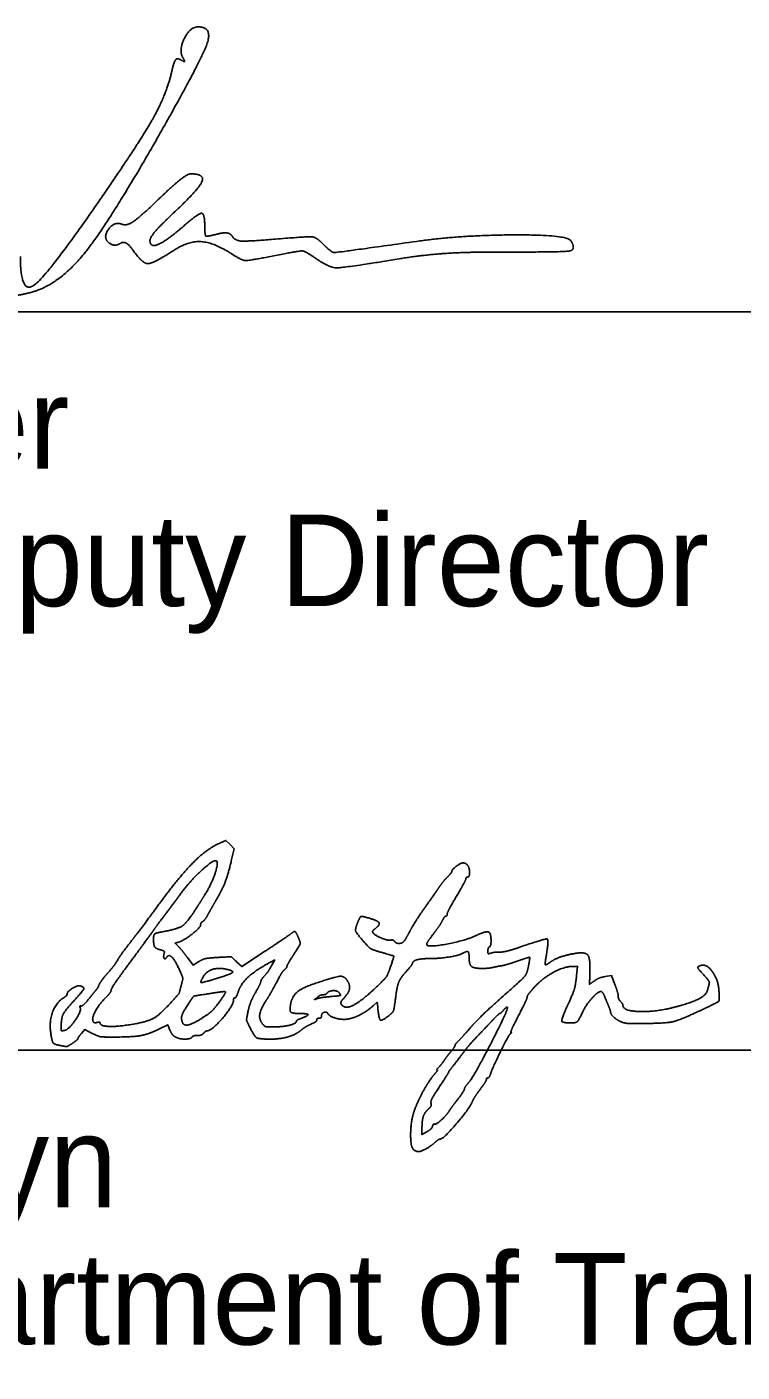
# Model space of a CAD drawing. Extents: x 0 to 34, y 0 to 22.
# Drawn here: x 25.807 to 26.9, y 8.607 to 10.664 of the extents above; entities that cross this region are included whole.
import ezdxf

# ---------------------------------------------------------------- set-up
doc = ezdxf.new("R2010")
doc.units = 0
for name, color, linetype in [('Default', 7, 'Continuous'), ('SH_Data', 7, 'Continuous'), ('SH_Text', 7, 'Continuous')]:
    doc.layers.add(name, color=color, linetype=linetype)

msp = doc.modelspace()

# ---------------------------------------------------------------- linework, layer by layer
at = {"layer": 'Default'}
for points in [[(26.0982, 9.4141), (26.1108, 9.42), (26.1172, 9.4136), (26.1235, 9.4072), (26.1191, 9.3885)], [(26.0383, 9.2641), (26.0332, 9.2626), (26.0384, 9.2574)], [(26.0521, 9.2407), (26.0606, 9.2292), (26.0694, 9.2345)], [(26.1272, 9.2344), (26.1354, 9.2268), (26.1716, 9.2509)], [(26.1811, 9.2292), (26.1856, 9.2371), (26.18, 9.2342)], [(26.647, 9.2133), (26.6484, 9.2271), (26.6406, 9.2271)], [(26.6908, 9.2116), (26.7005, 9.2132), (26.7055, 9.1996)], [(26.3429, 9.1655), (26.3422, 9.1723), (26.3363, 9.1672)], [(26.0252, 9.1299), (26.0219, 9.1379), (26.0081, 9.1311)], [(25.9066, 9.1248), (25.8951, 9.1306), (25.8901, 9.1248)], [(26.4106, 8.9794), (26.4106, 8.97), (26.4181, 8.9743)]]:
    msp.add_lwpolyline(points, dxfattribs=at)
for points in [[(26.0086, 9.3222), (26.0383, 9.3628), (26.0801, 9.4057), (26.0982, 9.4141)], [(26.0967, 9.3883), (26.0931, 9.392), (26.0545, 9.3562), (26.0391, 9.3349)], [(26.0784, 9.3363), (26.0879, 9.3511), (26.0998, 9.3852), (26.0967, 9.3883)], [(26.1191, 9.3885), (26.1141, 9.3674), (26.105, 9.3438), (26.0955, 9.3279)], [(26.4562, 9.3722), (26.4562, 9.375), (26.4694, 9.3853), (26.4731, 9.3854)], [(26.4731, 9.3854), (26.4752, 9.3854), (26.4781, 9.3842), (26.4797, 9.3826)], [(26.4797, 9.3826), (26.4832, 9.3791), (26.4836, 9.3639), (26.4802, 9.3639)], [(26.4358, 9.3469), (26.4398, 9.3527), (26.446, 9.3605), (26.4496, 9.3641)], [(26.4496, 9.3641), (26.4532, 9.3677), (26.4562, 9.3714), (26.4562, 9.3722)], [(26.4778, 9.3613), (26.4778, 9.36), (26.4713, 9.3479), (26.4634, 9.3345)], [(26.4802, 9.3639), (26.4789, 9.3639), (26.4778, 9.3627), (26.4778, 9.3613)], [(26.4142, 9.3159), (26.4221, 9.3271), (26.4319, 9.341), (26.4358, 9.3469)], [(25.9685, 9.2688), (25.9773, 9.2801), (25.9954, 9.3042), (26.0086, 9.3222)], [(26.0391, 9.3349), (26.0356, 9.33), (26.0261, 9.3173), (26.0182, 9.3068)], [(26.0679, 9.3196), (26.0712, 9.3248), (26.0759, 9.3323), (26.0784, 9.3363)], [(26.0955, 9.3279), (26.092, 9.3219), (26.0868, 9.3127), (26.084, 9.3075)], [(26.4634, 9.3345), (26.4555, 9.3211), (26.449, 9.3087), (26.449, 9.307)], [(26.0182, 9.3068), (26.0103, 9.2964), (26.0022, 9.2853), (26.0002, 9.2824)], [(26.0181, 9.2809), (26.0387, 9.2847), (26.0527, 9.2956), (26.0679, 9.3196)], [(26.084, 9.3075), (26.0811, 9.3022), (26.0773, 9.297), (26.0755, 9.2959)], [(26.3122, 9.2941), (26.3159, 9.3032), (26.319, 9.3042), (26.3317, 9.3004)], [(26.3317, 9.3004), (26.3437, 9.2969), (26.3466, 9.2907), (26.3389, 9.2849)], [(26.3928, 9.2823), (26.3966, 9.2895), (26.4063, 9.3046), (26.4142, 9.3159)], [(26.447, 9.3039), (26.4459, 9.3039), (26.4436, 9.3009), (26.4418, 9.2973)], [(26.449, 9.307), (26.449, 9.3053), (26.4481, 9.3039), (26.447, 9.3039)], [(26.0002, 9.2824), (25.9982, 9.2794), (25.9829, 9.2585), (25.9661, 9.2358)], [(26.0002, 9.2688), (26.0002, 9.2757), (26.0043, 9.2785), (26.0181, 9.2809)], [(26.0722, 9.2905), (26.0722, 9.2868), (26.0464, 9.2667), (26.0383, 9.2641)], [(26.0755, 9.2959), (26.0737, 9.2949), (26.0722, 9.2925), (26.0722, 9.2905)], [(26.2107, 9.2775), (26.2153, 9.2812), (26.2176, 9.2803), (26.2206, 9.2737)], [(26.322, 9.2647), (26.3104, 9.2778), (26.3082, 9.2845), (26.3122, 9.2941)], [(26.3389, 9.2849), (26.3362, 9.2828), (26.3347, 9.28), (26.3357, 9.2786)], [(26.3836, 9.2661), (26.3848, 9.2677), (26.389, 9.275), (26.3928, 9.2823)], [(26.4418, 9.2973), (26.44, 9.2936), (26.4338, 9.2845), (26.4282, 9.2771)], [(26.4954, 9.2752), (26.5084, 9.2814), (26.5162, 9.2783), (26.5162, 9.2669)], [(25.9469, 9.2394), (25.9499, 9.2442), (25.9596, 9.2574), (25.9685, 9.2688)], [(26.0112, 9.2524), (26.004, 9.2542), (26.0002, 9.2599), (26.0002, 9.2688)], [(26.1716, 9.2509), (26.1915, 9.2642), (26.2091, 9.2761), (26.2107, 9.2775)], [(26.2206, 9.2737), (26.225, 9.2641), (26.2241, 9.26), (26.2138, 9.2442)], [(26.3454, 9.2496), (26.3347, 9.2527), (26.3297, 9.2558), (26.322, 9.2647)], [(26.3357, 9.2786), (26.3383, 9.2748), (26.3583, 9.2666), (26.3629, 9.2674)], [(26.3629, 9.2674), (26.3651, 9.2678), (26.3677, 9.267), (26.3685, 9.2656)], [(26.3685, 9.2656), (26.3707, 9.2621), (26.3807, 9.2624), (26.3836, 9.2661)], [(26.4282, 9.2771), (26.4225, 9.2696), (26.4178, 9.2623), (26.4178, 9.261)], [(26.4178, 9.261), (26.4178, 9.2557), (26.4774, 9.2667), (26.4954, 9.2752)], [(26.5162, 9.2669), (26.5162, 9.2623), (26.5151, 9.2579), (26.5138, 9.2571)], [(26.5586, 9.2561), (26.5989, 9.27), (26.6048, 9.2684), (26.6007, 9.2445)], [(25.9306, 9.2175), (25.9372, 9.2249), (25.9415, 9.2306), (25.9469, 9.2394)], [(26.0163, 9.2462), (26.0172, 9.2497), (26.016, 9.2512), (26.0112, 9.2524)], [(26.0206, 9.2414), (26.0182, 9.2375), (26.015, 9.2411), (26.0163, 9.2462)], [(26.0394, 9.2228), (26.0332, 9.2365), (26.0235, 9.2461), (26.0206, 9.2414)], [(26.0384, 9.2574), (26.0412, 9.2546), (26.0474, 9.2471), (26.0521, 9.2407)], [(26.0694, 9.2345), (26.0759, 9.2383), (26.0835, 9.24), (26.0986, 9.2409)], [(26.0986, 9.2409), (26.1189, 9.2421), (26.1191, 9.242), (26.1272, 9.2344)], [(26.2138, 9.2442), (26.2085, 9.236), (26.2042, 9.2284), (26.2042, 9.2273)], [(26.3622, 9.2258), (26.3679, 9.2426), (26.3675, 9.2432), (26.3454, 9.2496)], [(26.4205, 9.2391), (26.409, 9.2391), (26.3962, 9.2353), (26.3962, 9.2319)], [(26.4712, 9.2464), (26.4656, 9.2435), (26.4354, 9.2391), (26.4205, 9.2391)], [(26.4826, 9.2417), (26.4826, 9.2491), (26.4789, 9.2506), (26.4712, 9.2464)], [(26.5019, 9.2241), (26.4895, 9.2241), (26.4826, 9.2304), (26.4826, 9.2417)], [(26.5138, 9.2571), (26.5125, 9.2562), (26.5114, 9.2534), (26.5114, 9.2508)], [(26.5114, 9.2508), (26.5114, 9.2468), (26.5124, 9.2463), (26.5168, 9.2477)], [(26.5168, 9.2477), (26.5198, 9.2486), (26.5256, 9.2493), (26.5298, 9.2491)], [(26.5298, 9.2491), (26.5339, 9.249), (26.5469, 9.2521), (26.5586, 9.2561)], [(26.5738, 9.2295), (26.5759, 9.241), (26.5742, 9.2414), (26.5532, 9.2342)], [(26.6007, 9.2445), (26.5994, 9.2369), (26.5987, 9.2303), (26.5991, 9.2298)], [(26.6067, 9.2337), (26.6139, 9.2387), (26.6322, 9.245), (26.6458, 9.2472)], [(26.6458, 9.2472), (26.6605, 9.2495), (26.6681, 9.2391), (26.6673, 9.2178)], [(25.9162, 9.1971), (25.9162, 9.1987), (25.9254, 9.2117), (25.9306, 9.2175)], [(25.9661, 9.2358), (25.9493, 9.2132), (25.9355, 9.193), (25.9354, 9.1911)], [(26.0427, 9.1983), (26.0452, 9.2081), (26.0449, 9.2103), (26.0394, 9.2228)], [(26.1104, 9.2231), (26.0996, 9.2253), (26.0822, 9.2202), (26.0778, 9.2136)], [(26.0998, 9.2096), (26.119, 9.2155), (26.123, 9.2206), (26.1104, 9.2231)], [(26.18, 9.2342), (26.1566, 9.2216), (26.1339, 9.201), (26.1298, 9.1885)], [(26.1683, 9.211), (26.1738, 9.217), (26.1763, 9.2206), (26.1811, 9.2292)], [(26.2007, 9.2223), (26.1987, 9.2207), (26.1956, 9.2165), (26.1938, 9.213)], [(26.2042, 9.2273), (26.2042, 9.2262), (26.2026, 9.2239), (26.2007, 9.2223)], [(26.3439, 9.1985), (26.3543, 9.2085), (26.3585, 9.2147), (26.3622, 9.2258)], [(26.3869, 9.2198), (26.3784, 9.2104), (26.3727, 9.1978), (26.3711, 9.1851)], [(26.3962, 9.2319), (26.3962, 9.231), (26.392, 9.2256), (26.3869, 9.2198)], [(26.5186, 9.2255), (26.5153, 9.2247), (26.5078, 9.2241), (26.5019, 9.2241)], [(26.5318, 9.2281), (26.5279, 9.2275), (26.5219, 9.2263), (26.5186, 9.2255)], [(26.529, 9.1766), (26.5645, 9.2081), (26.5714, 9.2163), (26.5738, 9.2295)], [(26.5532, 9.2342), (26.5454, 9.2315), (26.5358, 9.2287), (26.5318, 9.2281)], [(26.6406, 9.2271), (26.6279, 9.2271), (26.5942, 9.2086), (26.582, 9.1951)], [(26.5991, 9.2298), (26.5996, 9.2293), (26.603, 9.2311), (26.6067, 9.2337)], [(26.6673, 9.2178), (26.6667, 9.1994), (26.6665, 9.1997), (26.6743, 9.2052)], [(26.8374, 9.2185), (26.8321, 9.2241), (26.8319, 9.2268), (26.8365, 9.2285)], [(26.8365, 9.2285), (26.8451, 9.2318), (26.8635, 9.2069), (26.8645, 9.1906)], [(26.8465, 9.1893), (26.8505, 9.2011), (26.849, 9.206), (26.8374, 9.2185)], [(25.8682, 9.185), (25.8683, 9.1888), (25.885, 9.1988), (25.8888, 9.1973)], [(25.8888, 9.1973), (25.8948, 9.195), (25.8925, 9.1901), (25.8782, 9.1742)], [(25.9138, 9.1928), (25.9151, 9.1944), (25.9162, 9.1963), (25.9162, 9.1971)], [(26.023, 9.1678), (26.0391, 9.1853), (26.0394, 9.1859), (26.0427, 9.1983)], [(26.0778, 9.2136), (26.0708, 9.2029), (26.0754, 9.2021), (26.0998, 9.2096)], [(26.1559, 9.1869), (26.1603, 9.1946), (26.1641, 9.2023), (26.1643, 9.204)], [(26.1643, 9.204), (26.1646, 9.2058), (26.1664, 9.2089), (26.1683, 9.211)], [(26.1938, 9.213), (26.1856, 9.1976), (26.1779, 9.1838), (26.1717, 9.1741)], [(26.21, 9.1703), (26.2121, 9.1815), (26.2283, 9.1949), (26.2476, 9.2013)], [(26.2476, 9.2013), (26.2794, 9.2119), (26.2929, 9.2123), (26.2979, 9.2029)], [(26.2869, 9.1696), (26.2923, 9.161), (26.319, 9.1745), (26.3439, 9.1985)], [(26.2979, 9.2029), (26.3012, 9.1968), (26.2977, 9.1854), (26.2903, 9.1775)], [(26.6323, 9.1654), (26.6413, 9.1853), (26.6454, 9.1985), (26.647, 9.2133)], [(26.6743, 9.2052), (26.678, 9.2079), (26.6855, 9.2108), (26.6908, 9.2116)], [(26.7055, 9.1996), (26.7083, 9.1922), (26.7106, 9.184), (26.7106, 9.1815)], [(25.8434, 9.1234), (25.8404, 9.142), (25.8512, 9.172), (25.8636, 9.1797)], [(25.8636, 9.1797), (25.8661, 9.1813), (25.8682, 9.1837), (25.8682, 9.185)], [(25.8894, 9.1666), (25.8908, 9.1662), (25.8963, 9.1713), (25.9017, 9.1779)], [(25.9017, 9.1779), (25.907, 9.1845), (25.9125, 9.1912), (25.9138, 9.1928)], [(25.928, 9.1803), (25.9182, 9.1707), (25.9058, 9.1486), (25.9076, 9.1439)], [(25.9354, 9.1911), (25.9353, 9.1891), (25.932, 9.1843), (25.928, 9.1803)], [(26.0806, 9.1848), (26.0628, 9.1822), (26.0608, 9.1811), (26.0535, 9.1699)], [(26.098, 9.1875), (26.0924, 9.1866), (26.0846, 9.1854), (26.0806, 9.1848)], [(26.103, 9.1758), (26.1108, 9.1872), (26.1099, 9.1893), (26.098, 9.1875)], [(26.1246, 9.1791), (26.1235, 9.1791), (26.1226, 9.1777), (26.1226, 9.1761)], [(26.1298, 9.1885), (26.128, 9.1833), (26.1257, 9.1791), (26.1246, 9.1791)], [(26.1449, 9.1591), (26.1465, 9.1668), (26.1514, 9.1793), (26.1559, 9.1869)], [(26.2509, 9.1801), (26.2463, 9.1763), (26.2463, 9.1763), (26.251, 9.178)], [(26.2597, 9.1839), (26.2574, 9.1839), (26.2534, 9.1822), (26.2509, 9.1801)], [(26.251, 9.178), (26.2537, 9.1789), (26.2612, 9.1801), (26.2678, 9.1807)], [(26.2652, 9.186), (26.2645, 9.1848), (26.262, 9.1839), (26.2597, 9.1839)], [(26.2837, 9.1871), (26.2809, 9.1905), (26.2675, 9.1897), (26.2652, 9.186)], [(26.2678, 9.1807), (26.2845, 9.1823), (26.2869, 9.1832), (26.2837, 9.1871)], [(26.2903, 9.1775), (26.2876, 9.1746), (26.286, 9.1711), (26.2869, 9.1696)], [(26.3711, 9.1851), (26.3682, 9.1626), (26.3665, 9.1571), (26.3608, 9.1526)], [(26.4849, 9.1338), (26.4921, 9.1422), (26.512, 9.1614), (26.529, 9.1766)], [(26.5714, 9.1805), (26.5714, 9.1789), (26.5655, 9.1661), (26.5582, 9.1519)], [(26.582, 9.1951), (26.5762, 9.1886), (26.5714, 9.1821), (26.5714, 9.1805)], [(26.6838, 9.1887), (26.6795, 9.1887), (26.6613, 9.1682), (26.6565, 9.158)], [(26.6894, 9.1821), (26.6879, 9.1857), (26.6854, 9.1887), (26.6838, 9.1887)], [(26.6953, 9.1679), (26.6936, 9.1721), (26.6909, 9.1784), (26.6894, 9.1821)], [(26.7106, 9.1815), (26.7106, 9.179), (26.7122, 9.1754), (26.7142, 9.1734)], [(26.7977, 9.1651), (26.8213, 9.1713), (26.8443, 9.1827), (26.8465, 9.1893)], [(26.8645, 9.1906), (26.8655, 9.1753), (26.8628, 9.1722), (26.8394, 9.1612)], [(25.8782, 9.1742), (25.8645, 9.1591), (25.8595, 9.1489), (25.8589, 9.1351)], [(25.8638, 9.1291), (25.8701, 9.13), (25.8902, 9.1585), (25.8882, 9.1637)], [(25.8882, 9.1637), (25.8874, 9.1656), (25.888, 9.1669), (25.8894, 9.1666)], [(25.9665, 9.1384), (25.9892, 9.1421), (26.0089, 9.1523), (26.023, 9.1678)], [(26.0535, 9.1699), (26.0453, 9.1572), (26.0421, 9.1474), (26.0444, 9.1416)], [(26.0731, 9.1472), (26.0843, 9.1541), (26.0953, 9.1647), (26.103, 9.1758)], [(26.1226, 9.1761), (26.1224, 9.1675), (26.0893, 9.1287), (26.0822, 9.1287)], [(26.1469, 9.1351), (26.1425, 9.1442), (26.1423, 9.1464), (26.1449, 9.1591)], [(26.1717, 9.1741), (26.1638, 9.1615), (26.1615, 9.1463), (26.1666, 9.1395)], [(26.2236, 9.1551), (26.212, 9.1551), (26.208, 9.1596), (26.21, 9.1703)], [(26.2665, 9.1552), (26.2645, 9.1585), (26.257, 9.1554), (26.257, 9.1512)], [(26.3363, 9.1672), (26.327, 9.159), (26.3069, 9.1484), (26.2978, 9.1467)], [(26.3608, 9.1526), (26.3491, 9.1434), (26.3447, 9.1465), (26.3429, 9.1655)], [(26.4823, 9.05), (26.49, 9.0587), (26.5432, 9.1625), (26.5411, 9.1646)], [(26.5354, 9.1605), (26.533, 9.1575), (26.5304, 9.1551), (26.5296, 9.1551)], [(26.5411, 9.1646), (26.5404, 9.1653), (26.5378, 9.1634), (26.5354, 9.1605)], [(26.6396, 9.1407), (26.6251, 9.1407), (26.6235, 9.1461), (26.6323, 9.1654)], [(26.6565, 9.158), (26.6508, 9.1456), (26.646, 9.1407), (26.6396, 9.1407)], [(26.6987, 9.1583), (26.6986, 9.1594), (26.6971, 9.1637), (26.6953, 9.1679)], [(26.7144, 9.1427), (26.7073, 9.1461), (26.6988, 9.1545), (26.6987, 9.1583)], [(26.7142, 9.1734), (26.7162, 9.1714), (26.7178, 9.1687), (26.7178, 9.1674)], [(26.7178, 9.1674), (26.7178, 9.1589), (26.7684, 9.1574), (26.7977, 9.1651)], [(26.8394, 9.1612), (26.8046, 9.1449), (26.7836, 9.1401), (26.7442, 9.1397)], [(25.8589, 9.1351), (25.8587, 9.1295), (25.8595, 9.1285), (25.8638, 9.1291)], [(25.9076, 9.1439), (25.9085, 9.1415), (25.9108, 9.1406), (25.9138, 9.1414)], [(25.9138, 9.1414), (25.9165, 9.1421), (25.9186, 9.1417), (25.9186, 9.1406)], [(25.9186, 9.1406), (25.9186, 9.136), (25.9443, 9.1348), (25.9665, 9.1384)], [(26.0444, 9.1416), (26.0464, 9.1363), (26.06, 9.139), (26.0731, 9.1472)], [(26.1787, 9.1159), (26.1612, 9.116), (26.1542, 9.1203), (26.1469, 9.1351)], [(26.1666, 9.1395), (26.1695, 9.1357), (26.173, 9.1347), (26.1842, 9.1347)], [(26.1842, 9.1347), (26.1982, 9.1347), (26.2186, 9.1398), (26.2186, 9.1433)], [(26.2186, 9.1433), (26.2186, 9.1443), (26.2223, 9.1465), (26.2269, 9.1481)], [(26.2269, 9.1481), (26.2372, 9.1519), (26.2356, 9.1551), (26.2236, 9.1551)], [(26.2444, 9.1405), (26.2371, 9.1372), (26.2294, 9.1327), (26.2252, 9.1292)], [(26.2498, 9.1454), (26.2498, 9.144), (26.2474, 9.1418), (26.2444, 9.1405)], [(26.2534, 9.1479), (26.2514, 9.1479), (26.2498, 9.1468), (26.2498, 9.1454)], [(26.257, 9.1512), (26.257, 9.1494), (26.2554, 9.1479), (26.2534, 9.1479)], [(26.2978, 9.1467), (26.2892, 9.1452), (26.2694, 9.1505), (26.2665, 9.1552)], [(26.5208, 9.1473), (26.5168, 9.143), (26.5062, 9.1319), (26.4974, 9.1226)], [(26.5296, 9.1551), (26.5289, 9.1551), (26.5249, 9.1516), (26.5208, 9.1473)], [(26.5582, 9.1519), (26.5509, 9.1378), (26.5458, 9.1262), (26.5468, 9.1262)], [(26.7442, 9.1397), (26.7293, 9.1395), (26.719, 9.1406), (26.7144, 9.1427)], [(25.8599, 9.1057), (25.849, 9.1077), (25.8452, 9.1118), (25.8434, 9.1234)], [(25.885, 9.1172), (25.885, 9.1163), (25.8812, 9.1129), (25.8766, 9.1098)], [(25.8901, 9.1248), (25.8873, 9.1216), (25.885, 9.1182), (25.885, 9.1172)], [(25.9374, 9.1191), (25.9218, 9.1191), (25.9159, 9.1202), (25.9066, 9.1248)], [(26.0081, 9.1311), (25.9925, 9.1233), (25.9673, 9.1191), (25.9374, 9.1191)], [(26.0335, 9.1193), (26.0308, 9.1207), (26.0271, 9.1255), (26.0252, 9.1299)], [(26.059, 9.1191), (26.057, 9.1159), (26.0395, 9.116), (26.0335, 9.1193)], [(26.0673, 9.1215), (26.0635, 9.1215), (26.0598, 9.1204), (26.059, 9.1191)], [(26.077, 9.1251), (26.0754, 9.1231), (26.071, 9.1215), (26.0673, 9.1215)], [(26.0822, 9.1287), (26.081, 9.1287), (26.0787, 9.127), (26.077, 9.1251)], [(26.2252, 9.1292), (26.2175, 9.1228), (26.1932, 9.1159), (26.1787, 9.1159)], [(26.4665, 9.1134), (26.4694, 9.1162), (26.4777, 9.1254), (26.4849, 9.1338)], [(26.4974, 9.1226), (26.4886, 9.1134), (26.4787, 9.1021), (26.4754, 9.0976)], [(26.546, 9.1244), (26.5434, 9.1226), (26.5181, 9.0716), (26.5152, 9.0621)], [(26.5468, 9.1262), (26.5478, 9.1262), (26.5474, 9.1254), (26.546, 9.1244)], [(25.8766, 9.1098), (25.8701, 9.1053), (25.8665, 9.1044), (25.8599, 9.1057)], [(26.4442, 9.083), (26.4462, 9.0861), (26.4508, 9.0921), (26.4544, 9.0964)], [(26.4754, 9.0976), (26.4673, 9.0867), (26.4568, 9.0729), (26.4538, 9.0694)], [(26.4544, 9.0964), (26.458, 9.1006), (26.461, 9.105), (26.4611, 9.1062)], [(26.4611, 9.1062), (26.4611, 9.1073), (26.4635, 9.1106), (26.4665, 9.1134)], [(26.4364, 9.0731), (26.4387, 9.0755), (26.4422, 9.08), (26.4442, 9.083)], [(26.4004, 9.0107), (26.4063, 9.0255), (26.4234, 9.0554), (26.4306, 9.0633)], [(26.4306, 9.0633), (26.4332, 9.0662), (26.4347, 9.0687), (26.4338, 9.0687)], [(26.4338, 9.0687), (26.4329, 9.0687), (26.4341, 9.0706), (26.4364, 9.0731)], [(26.4514, 9.0655), (26.4514, 9.0649), (26.4451, 9.055), (26.4373, 9.0434)], [(26.4538, 9.0694), (26.4525, 9.0678), (26.4514, 9.066), (26.4514, 9.0655)], [(26.509, 9.0542), (26.509, 9.0528), (26.5047, 9.046), (26.4995, 9.0391)], [(26.5112, 9.0567), (26.51, 9.0567), (26.509, 9.0555), (26.509, 9.0542)], [(26.5152, 9.0621), (26.5142, 9.0591), (26.5125, 9.0567), (26.5112, 9.0567)], [(26.4373, 9.0434), (26.4287, 9.0303), (26.4237, 9.0206), (26.4244, 9.0179)], [(26.4652, 9.0238), (26.4708, 9.0312), (26.4754, 9.0383), (26.4754, 9.0397)], [(26.4754, 9.0397), (26.4754, 9.041), (26.4785, 9.0456), (26.4823, 9.05)], [(26.4995, 9.0391), (26.4943, 9.0322), (26.4892, 9.0242), (26.4881, 9.0214)], [(26.4244, 9.0179), (26.4251, 9.0153), (26.4235, 9.0117), (26.4208, 9.0093)], [(26.4881, 9.0214), (26.4845, 9.0116), (26.4433, 8.9631), (26.4386, 8.9631)], [(26.4526, 9.0066), (26.4539, 9.0087), (26.4596, 9.0165), (26.4652, 9.0238)], [(26.3986, 8.9462), (26.3927, 8.95), (26.3939, 8.9943), (26.4004, 9.0107)], [(26.4208, 9.0093), (26.4148, 9.0041), (26.4106, 8.9917), (26.4106, 8.9794)], [(26.4298, 8.9859), (26.4317, 8.9847), (26.4484, 8.9998), (26.4526, 9.0066)], [(26.4181, 8.9743), (26.4223, 8.9767), (26.4262, 8.9805), (26.4268, 8.9828)], [(26.4268, 8.9828), (26.4274, 8.9851), (26.4288, 8.9865), (26.4298, 8.9859)], [(26.4312, 8.9585), (26.425, 8.9528), (26.409, 8.9438), (26.4051, 8.9439)], [(26.4386, 8.9631), (26.4373, 8.9631), (26.4339, 8.961), (26.4312, 8.9585)], [(26.4051, 8.9439), (26.4035, 8.9439), (26.4006, 8.945), (26.3986, 8.9462)]]:
    msp.add_open_spline(points, degree=2, dxfattribs=at)
at = {"layer": 'SH_Data'}
for p, q in [((24.6129, 10.2283), (28.1129, 10.2283)), ((24.6129, 9.0989), (28.1129, 9.0989))]:
    msp.add_line(p, q, dxfattribs=at)
at = {"layer": 'SH_Text'}
for points in [[(26.013, 10.5062), (26.0728, 10.6121), (26.0911, 10.6641), (26.0684, 10.6641)], [(26.0684, 10.6641), (26.0559, 10.6641), (26.0384, 10.628), (26.0454, 10.6166)], [(26.0454, 10.6166), (26.0484, 10.6118), (26.0469, 10.6106), (26.0419, 10.6137)], [(26.0286, 10.5978), (26.0208, 10.5626), (25.9805, 10.4899), (25.9212, 10.4038)], [(26.0419, 10.6137), (26.0366, 10.617), (26.0315, 10.6109), (26.0286, 10.5978)], [(25.8097, 10.2572), (25.8535, 10.2675), (25.9333, 10.3653), (26.013, 10.5062)], [(26.057, 10.4393), (26.0522, 10.4393), (26.0292, 10.421), (26.006, 10.3986)], [(26.0337, 10.3823), (26.0695, 10.4159), (26.0791, 10.4393), (26.057, 10.4393)], [(25.9212, 10.4038), (25.839, 10.2846), (25.7967, 10.2537), (25.7967, 10.3132)], [(26.006, 10.3986), (25.9803, 10.3738), (25.9595, 10.3596), (25.9528, 10.3621)], [(25.9948, 10.3375), (25.9948, 10.342), (26.0123, 10.3622), (26.0337, 10.3823)], [(26.0786, 10.3585), (26.0786, 10.3792), (26.0684, 10.3789), (26.0438, 10.3574)], [(25.9528, 10.3621), (25.9395, 10.3672), (25.922, 10.34), (25.9338, 10.3327)], [(26.0438, 10.3574), (26.0196, 10.3364), (25.9948, 10.3263), (25.9948, 10.3375)], [(26.0972, 10.3471), (26.0819, 10.3433), (26.0786, 10.3453), (26.0786, 10.3585)], [(26.1211, 10.3431), (26.1181, 10.3481), (26.1078, 10.3498), (26.0972, 10.3471)], [(25.9338, 10.3327), (25.938, 10.3301), (25.9451, 10.3303), (25.9497, 10.3331)], [(25.9497, 10.3331), (25.9542, 10.3359), (25.963, 10.3309), (25.9692, 10.3221)], [(26.0283, 10.3206), (26.0527, 10.3368), (26.0926, 10.3347), (26.1218, 10.3157)], [(26.1867, 10.3395), (26.145, 10.336), (26.1248, 10.3371), (26.1211, 10.3431)], [(26.2594, 10.332), (26.249, 10.3425), (26.237, 10.3437), (26.1867, 10.3395)], [(26.4024, 10.3361), (26.2805, 10.319), (26.2726, 10.3188), (26.2594, 10.332)], [(26.6383, 10.337), (26.6325, 10.3463), (26.4706, 10.3457), (26.4024, 10.3361)], [(26.5331, 10.3198), (26.6246, 10.3195), (26.6468, 10.3231), (26.6383, 10.337)], [(25.9692, 10.3221), (25.9831, 10.3022), (25.9997, 10.3018), (26.0283, 10.3206)], [(26.1218, 10.3157), (26.1355, 10.3069), (26.1464, 10.3066), (26.1841, 10.314)], [(26.1841, 10.314), (26.2235, 10.3218), (26.2321, 10.3213), (26.2473, 10.3107)], [(26.2473, 10.3107), (26.2686, 10.2957), (26.2917, 10.2955), (26.3757, 10.3094)], [(26.3757, 10.3094), (26.4114, 10.3153), (26.4822, 10.32), (26.5331, 10.3198)], [(25.7788, 10.2753), (25.7873, 10.2552), (25.7913, 10.2529), (25.8097, 10.2572)]]:
    msp.add_open_spline(points, degree=2, dxfattribs=at)

# ---------------------------------------------------------------- texts
for s, p in [('Robert Weaver', (24.6129, 9.9883)), ('District       Deputy Director', (24.6129, 9.7783)), ('Pamela Boratyn', (24.6129, 8.8589)), ('Director, Department of Transportation', (24.6129, 8.6489))]:
    msp.add_text(s, height=0.14, dxfattribs=at).set_placement(p)

doc.saveas('drawing.dxf')
